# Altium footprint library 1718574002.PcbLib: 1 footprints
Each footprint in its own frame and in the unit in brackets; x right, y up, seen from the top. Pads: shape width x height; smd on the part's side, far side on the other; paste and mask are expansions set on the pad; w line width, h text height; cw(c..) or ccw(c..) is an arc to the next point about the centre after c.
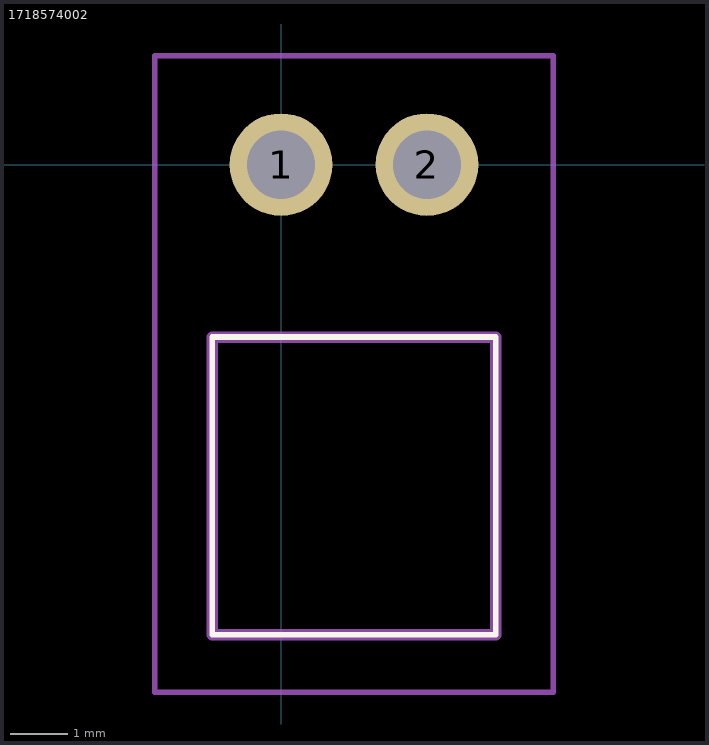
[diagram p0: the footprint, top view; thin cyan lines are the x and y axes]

## 1718574002 [mm]
pads (2):
  round 1.785 hole 1.19: 1(0,0) 2(2.54,0)
Top Overlay:
  lines w0.1: -1.195,-8.18 3.735,-8.18 3.735,-3 -1.195,-3 -1.195,-8.18
Mechanical 15:
  lines w0.2: -1.195,-8.18 3.735,-8.18 3.735,-3 -1.195,-3 -1.195,-8.18
Mechanical 20:
  lines w0.1: -2.195,-9.18 4.735,-9.18 4.735,1.893 -2.195,1.893 -2.195,-9.18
